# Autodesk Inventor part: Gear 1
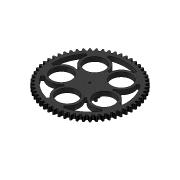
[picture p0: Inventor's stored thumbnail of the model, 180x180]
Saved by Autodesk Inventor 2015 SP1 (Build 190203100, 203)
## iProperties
Created: 2015-01
Part Number: Gear 1
Material: Generic
Document SubType Name: Modeling
Designer: Steve Brooks
Density: 1 g/cm^3
Appearance: Diamond plate 2 - Dark Gray
Author: Steve Brooks
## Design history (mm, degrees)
sketch "Sketch1"
  geometry: L1 (146.362, 64.159)-(146.732, 64.458); L2 (146.732, 64.458)-(147.1, 64.763); L3 (147.1, 64.763)-(147.829, 65.386); L4 (147.829, 65.386)-(149.262, 66.687); L5 (149.262, 66.687)-(150.663, 68.053); L6 (150.663, 68.053)-(152.032, 69.482); L7 (152.032, 69.482)-(153.371, 70.969); L8 (153.371, 70.969)-(154.68, 72.511); L9 (154.68, 72.511)-(152.999, 76.003); L10 (152.999, 76.003)-(150.977, 75.941); L11 (150.977, 75.941)-(148.98, 75.82); L12 (148.98, 75.82)-(147.009, 75.64); L13 (147.009, 75.64)-(145.067, 75.398); L14 (145.067, 75.398)-(143.157, 75.088); L15 (143.157, 75.088)-(142.215, 74.907); L16 (142.215, 74.907)-(141.748, 74.809); L17 (141.748, 74.809)-(141.282, 74.707); L18 (141.282, 74.707)-(138.297, 80.108); L19 (138.297, 80.108)-(138.632, 80.447); L20 (138.632, 80.447)-(138.963, 80.791); L21 (138.963, 80.791)-(139.618, 81.492); L22 (139.618, 81.492)-(140.896, 82.944); L23 (140.896, 82.944)-(142.135, 84.459); L24 (142.135, 84.459)-(143.336, 86.033); L25 (143.336, 86.033)-(144.5, 87.66); L26 (144.5, 87.66)-(145.628, 89.339); L27 (145.628, 89.339)-(143.566, 92.62); L28 (143.566, 92.62)-(141.564, 92.332); L29 (141.564, 92.332)-(139.593, 91.989); L30 (139.593, 91.989)-(137.655, 91.59); L31 (137.655, 91.59)-(135.752, 91.131); L32 (135.752, 91.131)-(133.889, 90.61); L33 (133.889, 90.61)-(132.973, 90.324); L34 (132.973, 90.324)-(132.519, 90.174); L35 (132.519, 90.174)-(132.069, 90.02); L36 (132.069, 90.02)-(128.498, 95.053); L37 (128.498, 95.053)-(128.792, 95.428); L38 (128.792, 95.428)-(129.083, 95.807); L39 (129.083, 95.807)-(129.655, 96.577); L40 (129.655, 96.577)-(130.763, 98.163); L41 (130.763, 98.163)-(131.824, 99.808); L42 (131.824, 99.808)-(132.841, 101.505); L43 (132.841, 101.505)-(133.816, 103.252); L44 (133.816, 103.252)-(134.749, 105.047); L45 (134.749, 105.047)-(132.332, 108.077); L46 (132.332, 108.077)-(130.375, 107.567); L47 (130.375, 107.567)-(128.455, 107.005); L48 (128.455, 107.005)-(126.574, 106.391); L49 (126.574, 106.391)-(124.734, 105.723); L50 (124.734, 105.723)-(122.941, 104.996); L51 (122.941, 104.996)-(122.063, 104.609); L52 (122.063, 104.609)-(121.629, 104.41); L53 (121.629, 104.41)-(121.199, 104.206); L54 (121.199, 104.206)-(117.086, 108.808); L55 (117.086, 108.808)-(117.337, 109.213); L56 (117.337, 109.213)-(117.583, 109.622); L57 (117.583, 109.622)-(118.066, 110.451); L58 (118.066, 110.451)-(118.989, 112.152); L59 (118.989, 112.152)-(119.859, 113.905); L60 (119.859, 113.905)-(120.68, 115.705); L61 (120.68, 115.705)-(121.453, 117.551); L62 (121.453, 117.551)-(122.179, 119.439); L63 (122.179, 119.439)-(119.439, 122.179); L64 (119.439, 122.179)-(117.551, 121.453)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; 1 further point
  constraints: 2020 end point, 4 midpoint
extrude "Extrusion1" new body sketch "Sketch1" distance "d0" = 18; taper "d1" = 0 deg
sketch "Sketch3"
  geometry: L1 (1.607, -170.051)-(-2.269, -170.051) reference; L2 (170.051, 2.268)-(170.051, -1.607) reference; L3 (-2.269, 170.713)-(1.607, 170.713) reference; L4 (170.051, 0.331)-(-170.713, 0.331); L5 (-170.713, -1.607)-(-170.713, 2.268) reference; L6 (-0.331, 170.713)-(-0.331, -170.051); C1 r 4 at (24.669, 0.331); C2 r 4 at (17.21, 17.678); C3 r 4 at (-0.331, 24.669); C4 r 4 at (-17.678, 17.21); C5 r 4 at (-24.669, -0.331); C6 r 4 at (-17.21, -17.678); C7 r 4 at (0.331, -24.669); C8 r 4 at (17.678, -17.21); 1 further point
  constraints: 8 centre point, 4 end point, 4 midpoint, 17 other
  dimensions: "d4" = 8 diameter of C1; "d7" = 360 deg dimension on point (0, 0) C1.centre (derived); "d12" = 25 distance from line of C7.centre L4
extrude "Extrusion3" cut sketch "Sketch3" distance "d10" = 10; taper "d11" = 0 deg
sketch "Sketch4"
  geometry: C1 r 4 at (0, 0); 1 further point
  constraints: 1 centre point, 1 coincident
  dimensions: "d13" = 8 diameter of C1
extrude "Extrusion4" cut sketch "Sketch4" stored distance "d14" = 10; taper "d15" = 0 deg
sketch "Sketch5"
  geometry: L1 (0, 0)-(-0.331, -170.051); L2 (1.607, -170.051)-(-2.269, -170.051) reference; L3 (33.567, -141.061)-(28.584, -132.391); L4 (-28.559, -132.409)-(-33.576, -141.059); L5 (144.53, -11.666)-(134.744, -13.726); L6 (117.103, -68.078)-(123.78, -75.522); L7 (55.758, 133.851)-(54.693, 123.908); L8 (100.932, 90.334)-(110.076, 94.384); L9 (-110.07, 94.391)-(-100.942, 90.306); L10 (-54.723, 123.907)-(-55.749, 133.854); L11 (-123.784, -75.514)-(-117.079, -68.096); L12 (-134.753, -13.756)-(-144.531, -11.657); L13 (-146.362, 64.159)-(-146.732, 64.458) reference; L14 (-148.724, 58.457)-(-146.362, 64.159) reference; L15 (-149.197, 58.507)-(-148.724, 58.457) reference; L16 (-149.673, 58.552)-(-149.197, 58.507) reference; L17 (-150.629, 58.626)-(-149.673, 58.552) reference; L18 (-152.562, 58.72)-(-150.629, 58.626) reference; L19 (-154.519, 58.744)-(-152.562, 58.72) reference; L20 (-156.497, 58.702)-(-154.519, 58.744) reference; L21 (-158.495, 58.598)-(-156.497, 58.702) reference; L22 (-160.512, 58.433)-(-158.495, 58.598) reference; L23 (-161.791, 54.775)-(-160.512, 58.433) reference; L24 (-160.318, 53.39)-(-161.791, 54.775) reference; L25 (-158.821, 52.062)-(-160.318, 53.39) reference; L26 (-157.3, 50.796)-(-158.821, 52.062) reference; L27 (-155.755, 49.594)-(-157.3, 50.796) reference; L28 (-154.186, 48.462)-(-155.755, 49.594) reference; L29 (-153.392, 47.925)-(-154.186, 48.462) reference; L30 (-152.992, 47.663)-(-153.392, 47.925) reference; L31 (-152.59, 47.407)-(-152.992, 47.663) reference; L32 (-154.299, 41.477)-(-152.59, 47.407) reference; L33 (-154.775, 41.473)-(-154.299, 41.477) reference; L34 (-155.252, 41.465)-(-154.775, 41.473) reference; L35 (-156.211, 41.432)-(-155.252, 41.465) reference; L36 (-158.142, 41.309)-(-156.211, 41.432) reference; L37 (-160.09, 41.113)-(-158.142, 41.309) reference; L38 (-162.051, 40.85)-(-160.09, 41.113) reference; L39 (-164.024, 40.523)-(-162.051, 40.85) reference; L40 (-166.01, 40.133)-(-164.024, 40.523) reference; L41 (-166.872, 36.355)-(-166.01, 40.133) reference; L42 (-165.253, 35.143)-(-166.872, 36.355) reference; L43 (-163.616, 33.992)-(-165.253, 35.143) reference; L44 (-161.964, 32.903)-(-163.616, 33.992) reference; L45 (-160.294, 31.883)-(-161.964, 32.903) reference; L46 (-158.607, 30.934)-(-160.294, 31.883) reference; L47 (-157.758, 30.488)-(-158.607, 30.934) reference; L48 (-157.331, 30.273)-(-157.758, 30.488) reference; L49 (-156.904, 30.063)-(-157.331, 30.273) reference; L50 (-157.938, 23.979)-(-156.904, 30.063) reference; L51 (-158.41, 23.922)-(-157.938, 23.979) reference; L52 (-158.884, 23.86)-(-158.41, 23.922) reference; L53 (-159.833, 23.721)-(-158.884, 23.86) reference; L54 (-161.738, 23.382)-(-159.833, 23.721) reference; L55 (-163.651, 22.969)-(-161.738, 23.382) reference; L56 (-165.571, 22.489)-(-163.651, 22.969) reference; L57 (-167.496, 21.942)-(-165.571, 22.489) reference; L58 (-169.425, 21.333)-(-167.496, 21.942) reference; L59 (-169.858, 17.482)-(-169.425, 21.333) reference; L60 (-168.113, 16.459)-(-169.858, 17.482) reference; L61 (-166.358, 15.498)-(-168.113, 16.459) reference; L62 (-164.594, 14.602)-(-166.358, 15.498) reference; L63 (-162.821, 13.774)-(-164.594, 14.602) reference; L64 (-161.038, 13.02)-(-162.821, 13.774) reference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; C1 r 4 at (0, 0) reference; C2 r 40 at (0, -91.367); C3 r 40 at (86.895, -28.234); C4 r 40 at (53.704, 73.918); C5 r 40 at (-53.704, 73.918); C6 r 40 at (-86.895, -28.234); C7 r 4 at (0, 0) reference; C8 r 4 at (0.331, -24.669) reference; C9 r 4 at (-24.669, -0.331) reference; C10 r 4 at (-0.331, 24.669) reference; C11 r 4 at (24.669, 0.331) reference; C12 r 4 at (17.21, 17.678) reference; C13 r 4 at (-17.678, 17.21) reference; C14 r 4 at (-17.21, -17.678) reference; C15 r 4 at (17.678, -17.21) reference; A1 r 50 centre (0, -91.367) between (28.584, -132.391) and (-28.559, -132.409); A2 r 50 centre (86.895, -28.234) between (134.744, -13.726) and (117.103, -68.078); A3 r 50 centre (53.704, 73.918) between (54.693, 123.908) and (100.932, 90.334); A4 r 50 centre (-53.704, 73.918) between (-100.942, 90.306) and (-54.723, 123.907); A5 r 50 centre (-86.895, -28.234) between (-117.079, -68.096) and (-134.753, -13.756); A6 r 75 centre (0, 0) between (41.025, -62.785) and (47.035, -58.419); A7 r 75 centre (0, 0) between (72.389, 19.616) and (70.094, 26.68); A8 r 75 centre (0, 0) between (3.714, 74.908) and (-3.714, 74.908); A9 r 75 centre (0, 0) between (-70.094, 26.68) and (-72.389, 19.616); A10 r 75 centre (0, 0) between (-47.035, -58.419) and (-41.025, -62.785); A11 r 145 centre (0, 0) between (144.53, -11.666) and (110.076, 94.384); A12 r 145 centre (0, 0) between (55.758, 133.851) and (-55.749, 133.854); A13 r 145 centre (0, 0) between (-110.07, 94.391) and (-144.531, -11.657); A14 r 145 centre (0, 0) between (-123.784, -75.514) and (-33.576, -141.059); A15 r 145 centre (0, 0) between (33.567, -141.061) and (123.78, -75.522)
  constraints: 40 point on circle, 22 end point, 20 centre point, 7 coincident, 1 equal length, 1 midpoint, 1 vertical alignment
  dimensions: "d16" = 30 deg angle of L3 L1; "d17" = 30 deg angle of L4 L1 (derived); "d18" = 10 distance of L3.start L3.end; "d21" = 10 radial gap between concentric circles of A1 C2; "d22" = 100 diameter of A1
extrude "Extrusion5" cut sketch "Sketch5" stored distance "d27" = 10; taper "d28" = 0 deg
sketch "Sketch6"
  geometry: C1 r 4 at (0, 0) reference; C2 r 35 at (0, 0)
  constraints: 1 centre point, 1 coincident
  dimensions: "d29" = 70 diameter of C2
extrude "Extrusion6" cut sketch "Sketch6" distance "d30" = 3; taper "d31" = 0 deg
sketch "Sketch7"
  geometry: C1 r 4 at (0, 0) reference; C2 r 35 at (0, 0) reference
extrude "Extrusion7" new body sketch "Sketch7" distance "d32" = 18; taper "d33" = 0 deg
sketch "Sketch8"
  geometry: L1 (-110.07, 94.391)-(-100.942, 90.306) reference; L2 (-134.753, -13.756)-(-144.531, -11.657) reference; L3 (144.53, -11.666)-(134.744, -13.726) reference; L4 (100.932, 90.334)-(110.076, 94.384) reference; L5 (117.103, -68.078)-(123.78, -75.522) reference; L6 (33.567, -141.061)-(28.584, -132.391) reference; L7 (-28.559, -132.409)-(-33.576, -141.059) reference; L8 (-123.784, -75.514)-(-117.079, -68.096) reference; L9 (55.758, 133.851)-(54.693, 123.908) reference; L10 (-54.723, 123.907)-(-55.749, 133.854) reference; L11 (-146.362, 64.159)-(-146.732, 64.458) reference; L12 (-148.724, 58.457)-(-146.362, 64.159) reference; L13 (-149.197, 58.507)-(-148.724, 58.457) reference; L14 (-149.673, 58.552)-(-149.197, 58.507) reference; L15 (-150.629, 58.626)-(-149.673, 58.552) reference; L16 (-152.562, 58.72)-(-150.629, 58.626) reference; L17 (-154.519, 58.744)-(-152.562, 58.72) reference; L18 (-156.497, 58.702)-(-154.519, 58.744) reference; L19 (-158.495, 58.598)-(-156.497, 58.702) reference; L20 (-160.512, 58.433)-(-158.495, 58.598) reference; L21 (-161.791, 54.775)-(-160.512, 58.433) reference; L22 (-160.318, 53.39)-(-161.791, 54.775) reference; L23 (-158.821, 52.062)-(-160.318, 53.39) reference; L24 (-157.3, 50.796)-(-158.821, 52.062) reference; L25 (-155.755, 49.594)-(-157.3, 50.796) reference; L26 (-154.186, 48.462)-(-155.755, 49.594) reference; L27 (-153.392, 47.925)-(-154.186, 48.462) reference; L28 (-152.992, 47.663)-(-153.392, 47.925) reference; L29 (-152.59, 47.407)-(-152.992, 47.663) reference; L30 (-154.299, 41.477)-(-152.59, 47.407) reference; L31 (-154.775, 41.473)-(-154.299, 41.477) reference; L32 (-155.252, 41.465)-(-154.775, 41.473) reference; L33 (-156.211, 41.432)-(-155.252, 41.465) reference; L34 (-158.142, 41.309)-(-156.211, 41.432) reference; L35 (-160.09, 41.113)-(-158.142, 41.309) reference; L36 (-162.051, 40.85)-(-160.09, 41.113) reference; L37 (-164.024, 40.523)-(-162.051, 40.85) reference; L38 (-166.01, 40.133)-(-164.024, 40.523) reference; L39 (-166.872, 36.355)-(-166.01, 40.133) reference; L40 (-165.253, 35.143)-(-166.872, 36.355) reference; L41 (-163.616, 33.992)-(-165.253, 35.143) reference; L42 (-161.964, 32.903)-(-163.616, 33.992) reference; L43 (-160.294, 31.883)-(-161.964, 32.903) reference; L44 (-158.607, 30.934)-(-160.294, 31.883) reference; L45 (-157.758, 30.488)-(-158.607, 30.934) reference; L46 (-157.331, 30.273)-(-157.758, 30.488) reference; L47 (-156.904, 30.063)-(-157.331, 30.273) reference; L48 (-157.938, 23.979)-(-156.904, 30.063) reference; L49 (-158.41, 23.922)-(-157.938, 23.979) reference; L50 (-158.884, 23.86)-(-158.41, 23.922) reference; L51 (-159.833, 23.721)-(-158.884, 23.86) reference; L52 (-161.738, 23.382)-(-159.833, 23.721) reference; L53 (-163.651, 22.969)-(-161.738, 23.382) reference; L54 (-165.571, 22.489)-(-163.651, 22.969) reference; L55 (-167.496, 21.942)-(-165.571, 22.489) reference; L56 (-169.425, 21.333)-(-167.496, 21.942) reference; L57 (-169.858, 17.482)-(-169.425, 21.333) reference; L58 (-168.113, 16.459)-(-169.858, 17.482) reference; L59 (-166.358, 15.498)-(-168.113, 16.459) reference; L60 (-164.594, 14.602)-(-166.358, 15.498) reference; L61 (-162.821, 13.774)-(-164.594, 14.602) reference; L62 (-161.038, 13.02)-(-162.821, 13.774) reference; L63 (-160.144, 12.672)-(-161.038, 13.02) reference; L64 (-159.697, 12.506)-(-160.144, 12.672) reference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; C1 r 35 at (0, 0) reference; C2 r 40 at (-53.704, 73.918) reference; C3 r 40 at (86.895, -28.234) reference; C4 r 40 at (0, -91.367) reference; C5 r 40 at (53.704, 73.918) reference; C6 r 40 at (-86.895, -28.234) reference; C7 r 4 at (-24.669, -0.331) reference; C8 r 4 at (-17.678, 17.21) reference; C9 r 4 at (-0.331, 24.669) reference; C10 r 4 at (17.21, 17.678) reference; C11 r 4 at (24.669, 0.331) reference; C12 r 4 at (17.678, -17.21) reference; C13 r 4 at (0.331, -24.669) reference; C14 r 4 at (-17.21, -17.678) reference; C15 r 17.5 at (0, 0); A1 r 145 centre (0, 0) between (-110.07, 94.391) and (-144.531, -11.657) reference; A2 r 50 centre (-53.704, 73.918) between (-100.942, 90.306) and (-70.094, 26.68) reference; A3 r 75 centre (0, 0) between (-70.094, 26.68) and (-72.389, 19.616) reference; A4 r 50 centre (-86.895, -28.234) between (-72.389, 19.616) and (-134.753, -13.756) reference; A5 r 145 centre (0, 0) between (144.53, -11.666) and (110.076, 94.384) reference; A6 r 50 centre (86.895, -28.234) between (134.744, -13.726) and (72.389, 19.616) reference; A7 r 75 centre (0, 0) between (72.389, 19.616) and (70.094, 26.68) reference; A8 r 50 centre (53.704, 73.918) between (70.094, 26.68) and (100.932, 90.334) reference; A9 r 145 centre (0, 0) between (33.567, -141.061) and (123.78, -75.522) reference; A10 r 50 centre (0, -91.367) between (28.584, -132.391) and (41.025, -62.785) reference; A11 r 75 centre (0, 0) between (41.025, -62.785) and (47.035, -58.419) reference; A12 r 50 centre (86.895, -28.234) between (47.035, -58.419) and (117.103, -68.078) reference; A13 r 75 centre (0, 0) between (-47.035, -58.419) and (-41.025, -62.785) reference; A14 r 50 centre (0, -91.367) between (-41.025, -62.785) and (-28.559, -132.409) reference; A15 r 145 centre (0, 0) between (-123.784, -75.514) and (-33.576, -141.059) reference; A16 r 50 centre (-86.895, -28.234) between (-117.079, -68.096) and (-47.035, -58.419) reference; A17 r 145 centre (0, 0) between (55.758, 133.851) and (-55.749, 133.854) reference; A18 r 50 centre (53.704, 73.918) between (54.693, 123.908) and (3.714, 74.908) reference; A19 r 75 centre (0, 0) between (3.714, 74.908) and (-3.714, 74.908) reference; A20 r 50 centre (-53.704, 73.918) between (-3.714, 74.908) and (-54.723, 123.907) reference; A21 r 24.672 centre (0, 0) between (-17.21, -17.678) and (-24.669, -0.331); A22 r 5 centre (0.331, -24.669) between (-4.08, -22.314) and (4.677, -22.197); A23 r 5 centre (17.678, -17.21) between (12.894, -18.663) and (19.003, -12.388); A24 r 5 centre (24.669, 0.331) between (22.314, -4.08) and (22.197, 4.677); A25 r 5 centre (17.21, 17.678) between (18.663, 12.894) and (12.388, 19.003); A26 r 5 centre (-0.331, 24.669) between (4.08, 22.314) and (-4.677, 22.197); A27 r 5 centre (-17.678, 17.21) between (-12.894, 18.663) and (-19.003, 12.388); A28 r 5 centre (-24.669, -0.331) between (-22.314, 4.08) and (-22.197, -4.677); A29 r 5 centre (-17.21, -17.678) between (-18.663, -12.894) and (-12.388, -19.003); A30 r 4.5 centre (-8.049, -20.195) between (-4.08, -22.314) and (-12.388, -19.003); A31 r 4.5 centre (8.588, -19.972) between (12.894, -18.663) and (4.677, -22.197); A32 r 4.5 centre (20.195, -8.049) between (22.314, -4.08) and (19.003, -12.388); A33 r 4.5 centre (19.972, 8.588) between (18.663, 12.894) and (22.197, 4.677); A34 r 4.5 centre (8.049, 20.195) between (4.08, 22.314) and (12.388, 19.003); A35 r 4.5 centre (-8.588, 19.972) between (-12.894, 18.663) and (-4.677, 22.197); A36 r 4.5 centre (-20.195, 8.049) between (-22.314, 4.08) and (-19.003, 12.388); A37 r 4.5 centre (-19.972, -8.588) between (-18.663, -12.894) and (-22.197, -4.677); 2 further points
  constraints: 36 point on circle, 32 end point, 18 centre point, 14 equal radius, 10 point on line, 9 coincident, 1 tangent, 59 other
  dimensions: "d47" = 10 diameter of A22; "d54" = 360 deg dimension on point (0, 0) L1019.end (derived); "d56" = 35 diameter of C15; "d60" = 4.5 radius of A30
extrude "Extrusion8" new body sketch "Sketch8" distance "d61" = 18; taper "d62" = 0 deg
sketch "Sketch10"
  geometry: C1 r 4 at (0, 0) reference; 1 further point
extrude "Extrusion10" cut sketch "Sketch10" stored distance "d65" = 18; taper "d66" = 0 deg
body "Solid1"
node "Projected Loop1"
body "Solid2"
node "Projected Loop2"
body "Solid3"
